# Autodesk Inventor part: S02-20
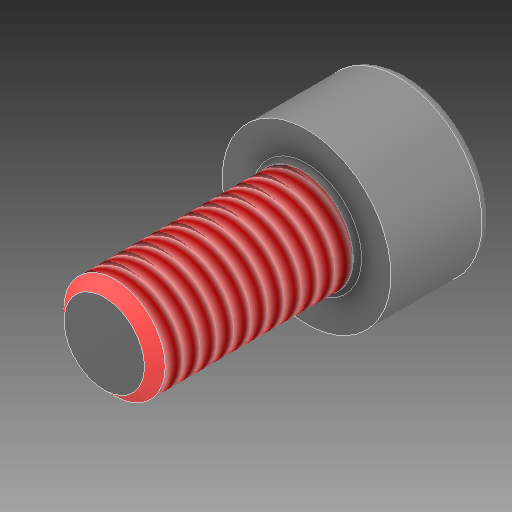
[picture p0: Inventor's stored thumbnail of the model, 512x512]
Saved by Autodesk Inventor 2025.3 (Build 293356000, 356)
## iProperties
Manager: ISO 4762 (DIN 912)
Created: 2025-04
Part Number: S02-20
Material: Všeobecné
Document SubType Name: Modeling
Designer: Patrik
Density: 1 g/cm^3
Appearance: Výchozí
Description: Imbusový šroub s válcovou hlavou
Stock Number: E 1200/6x12
Mass: 0.740201 g
Surface Area: 6.06212 cm^2
Volume: 0.740201 cm^3
User Status: 12.9
Sending System: KiM GmbH
Major Version: 4.0
Minor Version: 0.0
Format Version: 0.0
Product Id: KiM GmbH
cc_prop_force_one_body: 1
Hersteller: Meusburger
Material: 12.9 ISO 4762 (DIN 912)
Bestellnummer: E 1200/6x12
Teilenummer: E 1200/6x12
Beschreibung: Zylinderkopfschraube mit Innensechskant _ Cylinder head screw with hexagon socket
Author: Patrik
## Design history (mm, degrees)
feature "E 1200_6x12_1_1:1"
feature "Závit1" dims "d0" = 11.135, "d1" = 0
node "Těleso1"
